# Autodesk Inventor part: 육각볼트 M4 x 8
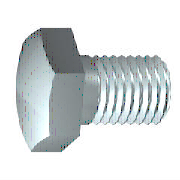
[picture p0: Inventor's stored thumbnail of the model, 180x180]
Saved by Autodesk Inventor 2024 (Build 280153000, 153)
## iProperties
Created: 2012-02
Part Number: 육각볼트 M4 x 8
Material: 강철, 연강
Description: 6각 머리 나사
Document SubType Name: Modeling
Standard: ISO 4017
Designer: mduedu
Standard Revision: Third edition 1999-08-15
Standards Organization: ISO
Language: ko-KR
Size Designation: M4 x 10
Categories: <MemberInstance><Categories><Category DisplayName="조임쇠" InternalName="e4da775c-781d-43d5-af7c-5136215cf5a6" Mnemonic="FSTN"><Category DisplayName="볼트" InternalN
Density: 7.86 g/cm^3
Appearance: 반광택
IsCustomPart: 0
Author: mduedu
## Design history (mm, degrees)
body "Solid1"
workplane "Work Plane1"
revolve "본체" stored, may be unused: angle "d12" = 90 deg
sketch "스케치2"
  geometry: L1 (0, 4.041)-(3.5, 2.021); L2 (3.5, 2.021)-(3.5, -2.021); L3 (3.5, -2.021)-(0, -4.041); L4 (0, -4.041)-(-3.5, -2.021); L5 (-3.5, -2.021)-(-3.5, 2.021); L6 (-3.5, 2.021)-(0, 4.041); 2 further points
  constraints: 12 end point, 1 coincident, 1 vertical, 11 other
  dimensions: "d11" = 7 distance between parallel lines of L5 L2 (= SW)
extrude "머리" join sketch "스케치2" distance "d3" = 2.4 (= KOH - SD); taper "d4" = 0 deg
revolve "모따기1" stored, may be unused: angle "d21" = 90 deg
feature "스레드" dims "d15" = 6.25 (= GEL), "d16" = 0
chamfer "모따기2" distance "d6" = 0.42941 (= -0.5 x SPD + 0.5 x GD); stored, may be unused: second distance "d7" = 0.42952 (computed from GUL), angle "d55" = 45 deg
sketch "스케치1"
  geometry: L1 (0, 3.015)-(0, 2); L2 (1.75, 2)-(8, 2); L3 (8, 2)-(8, 0); L4 (8, 0)-(-0.4, 0); L5 (-2.08, 0)-(9.68, 0) reference; L6 (-0.4, 0)-(-0.4, 3.015); L7 (-0.4, 3.015)-(0, 3.015); L8 (1.75, 2)-(1.32, 2); L9 (1.32, 2)-(0, 2); L10 (0, -0.603)-(0, 3.618) reference
  constraints: 16 end point, 2 collinear, 2 perpendicular, 1 parallel
  dimensions: "d0" = 8 distance between parallel lines of L3 L1 (= NLG); "d1" = 6.25 distance from line of L2.start L3 (= GEL); "d2" = 4 diameter of L2 L4 (= GD); "d9" = 0.4001 distance between parallel lines of L6 L1 (computed from SD); "d10" = 6.03 diameter of L7 L4 (= SD2); "d13" = 0.42952 distance of L2.start L8.end (computed from GAL); "d14" = 4 diameter of L9 L4 (= BDM)
sketch "스케치4"
  geometry: L1 (-2.8, 3.5)-(-2.8, 4.041); L2 (-2.8, 4.041)-(-2.487, 4.041); L3 (-2.487, 4.041)-(-2.8, 3.5); L4 (-3.28, 0)-(0.08, 0) reference; L5 (-0.4, 4.041)-(-2.8, 4.041) reference; L6 (-2.8, 2.021)-(-2.8, 4.041) reference
  constraints: 6 end point, 2 collinear, 1 perpendicular, 1 vertical
  dimensions: "d5" = 30 deg angle of L3 L1 (= ANG1); "d19" = 7 diameter of L1.start L4 (= SW0)
other parameters: "NLG" = 8 [user parameter; used in 1 equation term], "GD" = 4 (= NND) [user parameter; used in 2 equation terms], "BDM" = 4 (= NND) [user parameter; used in 1 equation term], "KOH" = 2.8 [user parameter; used in 1 equation term], "GEL" = 6.25 [user parameter; used in 2 equation terms], "SW" = 7 [user parameter; used in 2 equation terms], "SW0" = 7 (= SW) [user parameter; used in 1 equation term], "SPD" = 3.14117 (= NND - 1.2269 x PTC) [user parameter; used in 1 equation term], "SD2" = 6.03 [user parameter; used in 2 equation terms], "SD" = 0.4 [user parameter; used in 2 equation terms], "ANG1" = 30 deg [user parameter; used in 1 equation term], "GAL" = 0.42941 (= 0.61345 x PTC) [user parameter; used in 1 equation term], "GUL" = 0.42941 (= 0.61345 x PTC) [user parameter; used in 1 equation term], "d8" = 0, "RR" = 0.2 [user parameter], "d57" = 0, "d58" = 0, "TPU" = 14.28571 (computed from PTC) [user parameter], "GD1" = 3.14117 (= THREADDIA - 1.2269 x PTC) [user parameter], "THREADDIA" = 4 [user parameter; used in 1 equation term], "SDH" = 6.03 (= SD2) [user parameter], "SDHG" = 2.1 [user parameter], "TOA" = 30 deg [user parameter], "PTC" = 0.7 [user parameter; used in 5 equation terms], "NND" = 4 [user parameter; used in 3 equation terms], "E0" = 8.085 [user parameter]
